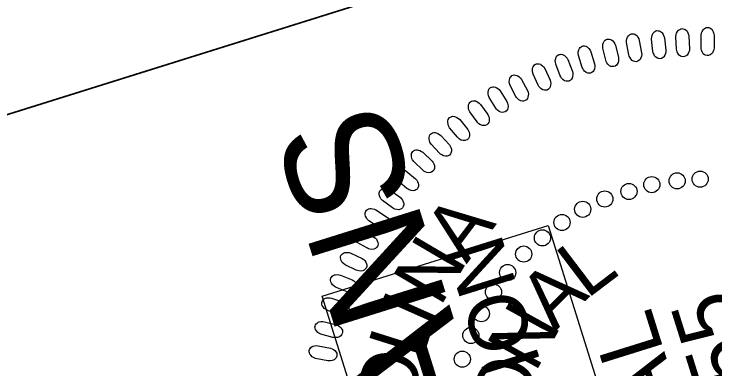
# Model space of a CAD drawing. Extents: x 473667 to 478950, y 494687 to 505998.
# Drawn here: x 473738.2 to 473807.7, y 505649.4 to 505684.6 of the extents above; entities that cross this region are included whole.
import ezdxf

# ---------------------------------------------------------------- set-up
doc = ezdxf.new("R2010")
doc.units = 0
for name, color, linetype in [('Sheet PE Seal Cell', 7, 'Continuous'), ('Sheet Plan CELL', 7, 'Continuous'), ('Sheet Plan Layout CELL', 7, 'Continuous'), ('Sheet Sticker Incomplete CELL', 7, 'Continuous')]:
    doc.layers.add(name, color=color, linetype=linetype)

msp = doc.modelspace()

# ---------------------------------------------------------------- linework, layer by layer
at = {"layer": 'Sheet PE Seal Cell'}
for points in [[(473803.877, 505681.09), (473803.813, 505682.316), (473803.839, 505682.536), (473803.883, 505682.679), (473803.987, 505682.854), (473804.078, 505682.968), (473804.187, 505683.054), (473804.288, 505683.099), (473804.4, 505683.124), (473804.512, 505683.111), (473804.634, 505683.087), (473804.741, 505683.033), (473804.851, 505682.938), (473804.915, 505682.862), (473804.99, 505682.716), (473805.059, 505682.54), (473805.09, 505682.382), (473805.162, 505681.127), (473805.148, 505680.956), (473805.111, 505680.815), (473805.03, 505680.651), (473804.925, 505680.506), (473804.833, 505680.421), (473804.678, 505680.353), (473804.53, 505680.325), (473804.379, 505680.357), (473804.272, 505680.402), (473804.139, 505680.495), (473804.012, 505680.658), (473803.934, 505680.834), (473803.899, 505680.961)], [(473806.306, 505681.251), (473806.32, 505682.478), (473806.359, 505682.697), (473806.413, 505682.837), (473806.527, 505683.005), (473806.625, 505683.113), (473806.739, 505683.192), (473806.843, 505683.231), (473806.955, 505683.249), (473807.067, 505683.228), (473807.187, 505683.196), (473807.291, 505683.136), (473807.394, 505683.035), (473807.453, 505682.955), (473807.519, 505682.804), (473807.577, 505682.624), (473807.598, 505682.464), (473807.591, 505681.208), (473807.567, 505681.039), (473807.52, 505680.899), (473807.429, 505680.741), (473807.316, 505680.602), (473807.218, 505680.523), (473807.06, 505680.465), (473806.91, 505680.447), (473806.761, 505680.489), (473806.657, 505680.54), (473806.531, 505680.641), (473806.414, 505680.812), (473806.348, 505680.992), (473806.32, 505681.121)], [(473799.142, 505680.527), (473798.925, 505681.735), (473798.924, 505681.957), (473798.95, 505682.104), (473799.03, 505682.291), (473799.107, 505682.416), (473799.203, 505682.514), (473799.299, 505682.572), (473799.406, 505682.611), (473799.519, 505682.611), (473799.643, 505682.603), (473799.756, 505682.563), (473799.877, 505682.483), (473799.95, 505682.415), (473800.043, 505682.28), (473800.133, 505682.114), (473800.183, 505681.96), (473800.412, 505680.725), (473800.421, 505680.554), (473800.401, 505680.409), (473800.341, 505680.236), (473800.255, 505680.079), (473800.174, 505679.983), (473800.03, 505679.896), (473799.886, 505679.85), (473799.732, 505679.863), (473799.62, 505679.894), (473799.477, 505679.969), (473799.33, 505680.115), (473799.232, 505680.28), (473799.18, 505680.402)], [(473801.538, 505680.862), (473801.399, 505682.08), (473801.41, 505682.302), (473801.445, 505682.447), (473801.538, 505682.629), (473801.622, 505682.749), (473801.724, 505682.841), (473801.824, 505682.893), (473801.933, 505682.925), (473802.046, 505682.918), (473802.169, 505682.902), (473802.28, 505682.855), (473802.395, 505682.767), (473802.464, 505682.695), (473802.548, 505682.555), (473802.627, 505682.383), (473802.668, 505682.227), (473802.819, 505680.98), (473802.816, 505680.809), (473802.788, 505680.665), (473802.717, 505680.496), (473802.622, 505680.344), (473802.534, 505680.254), (473802.385, 505680.177), (473802.239, 505680.14), (473802.086, 505680.162), (473801.976, 505680.2), (473801.838, 505680.284), (473801.701, 505680.439), (473801.613, 505680.61), (473801.569, 505680.735)], [(473796.86, 505679.987), (473796.567, 505681.178), (473796.552, 505681.399), (473796.569, 505681.548), (473796.637, 505681.74), (473796.706, 505681.87), (473796.796, 505681.973), (473796.887, 505682.037), (473796.992, 505682.083), (473797.105, 505682.09), (473797.229, 505682.09), (473797.345, 505682.057), (473797.47, 505681.984), (473797.547, 505681.921), (473797.648, 505681.792), (473797.749, 505681.632), (473797.809, 505681.482), (473798.115, 505680.263), (473798.134, 505680.094), (473798.123, 505679.947), (473798.075, 505679.771), (473797.998, 505679.609), (473797.923, 505679.508), (473797.785, 505679.412), (473797.644, 505679.357), (473797.49, 505679.361), (473797.376, 505679.384), (473797.229, 505679.451), (473797.073, 505679.587), (473796.964, 505679.746), (473796.905, 505679.864)], [(473794.52, 505679.288), (473794.154, 505680.46), (473794.125, 505680.68), (473794.133, 505680.829), (473794.189, 505681.024), (473794.249, 505681.158), (473794.332, 505681.267), (473794.42, 505681.336), (473794.522, 505681.389), (473794.634, 505681.403), (473794.757, 505681.411), (473794.875, 505681.385), (473795.005, 505681.321), (473795.085, 505681.263), (473795.195, 505681.14), (473795.305, 505680.987), (473795.374, 505680.841), (473795.757, 505679.644), (473795.786, 505679.476), (473795.784, 505679.328), (473795.746, 505679.149), (473795.682, 505678.983), (473795.613, 505678.878), (473795.481, 505678.774), (473795.344, 505678.71), (473795.189, 505678.704), (473795.075, 505678.72), (473794.923, 505678.777), (473794.759, 505678.904), (473794.641, 505679.055), (473794.573, 505679.169)], [(473792.341, 505678.45), (473791.903, 505679.595), (473791.859, 505679.813), (473791.857, 505679.962), (473791.901, 505680.161), (473791.953, 505680.298), (473792.03, 505680.412), (473792.113, 505680.487), (473792.21, 505680.546), (473792.322, 505680.567), (473792.444, 505680.582), (473792.563, 505680.564), (473792.697, 505680.508), (473792.781, 505680.455), (473792.898, 505680.34), (473793.018, 505680.193), (473793.096, 505680.053), (473793.553, 505678.882), (473793.592, 505678.715), (473793.6, 505678.569), (473793.574, 505678.388), (473793.519, 505678.218), (473793.457, 505678.108), (473793.332, 505677.996), (473793.199, 505677.924), (473793.046, 505677.908), (473792.93, 505677.917), (473792.775, 505677.964), (473792.604, 505678.08), (473792.476, 505678.223), (473792.402, 505678.334)], [(473790.157, 505677.51), (473789.648, 505678.626), (473789.59, 505678.841), (473789.579, 505678.99), (473789.611, 505679.19), (473789.654, 505679.331), (473789.722, 505679.45), (473789.801, 505679.53), (473789.895, 505679.594), (473790.005, 505679.623), (473790.126, 505679.645), (473790.247, 505679.635), (473790.383, 505679.587), (473790.47, 505679.54), (473790.594, 505679.431), (473790.723, 505679.293), (473790.81, 505679.157), (473791.34, 505678.018), (473791.389, 505677.854), (473791.406, 505677.708), (473791.391, 505677.526), (473791.347, 505677.352), (473791.292, 505677.24), (473791.175, 505677.119), (473791.046, 505677.039), (473790.894, 505677.014), (473790.778, 505677.016), (473790.621, 505677.053), (473790.442, 505677.158), (473790.306, 505677.293), (473790.225, 505677.399)], [(473787.949, 505676.401), (473787.37, 505677.482), (473787.299, 505677.693), (473787.279, 505677.841), (473787.298, 505678.044), (473787.332, 505678.186), (473787.393, 505678.31), (473787.466, 505678.394), (473787.556, 505678.465), (473787.664, 505678.5), (473787.784, 505678.53), (473787.904, 505678.527), (473788.043, 505678.488), (473788.134, 505678.447), (473788.264, 505678.346), (473788.401, 505678.216), (473788.496, 505678.086), (473789.097, 505676.982), (473789.157, 505676.821), (473789.183, 505676.677), (473789.179, 505676.494), (473789.146, 505676.319), (473789.099, 505676.202), (473788.988, 505676.075), (473788.865, 505675.987), (473788.715, 505675.952), (473788.6, 505675.946), (473788.44, 505675.974), (473788.255, 505676.067), (473788.11, 505676.194), (473788.024, 505676.294)], [(473785.95, 505675.241), (473785.305, 505676.284), (473785.221, 505676.489), (473785.191, 505676.636), (473785.197, 505676.84), (473785.222, 505676.984), (473785.276, 505677.11), (473785.343, 505677.199), (473785.428, 505677.275), (473785.534, 505677.318), (473785.652, 505677.355), (473785.771, 505677.36), (473785.913, 505677.33), (473786.006, 505677.294), (473786.142, 505677.202), (473786.288, 505677.08), (473786.391, 505676.957), (473787.059, 505675.892), (473787.129, 505675.737), (473787.164, 505675.594), (473787.172, 505675.411), (473787.151, 505675.234), (473787.11, 505675.114), (473787.008, 505674.981), (473786.891, 505674.885), (473786.743, 505674.841), (473786.628, 505674.828), (473786.468, 505674.846), (473786.277, 505674.927), (473786.125, 505675.044), (473786.031, 505675.139)], [(473784.099, 505673.88), (473783.389, 505674.881), (473783.292, 505675.081), (473783.254, 505675.225), (473783.248, 505675.429), (473783.263, 505675.574), (473783.308, 505675.704), (473783.37, 505675.797), (473783.451, 505675.878), (473783.553, 505675.927), (473783.668, 505675.972), (473783.788, 505675.984), (473783.931, 505675.963), (473784.026, 505675.933), (473784.168, 505675.849), (473784.32, 505675.738), (473784.432, 505675.621), (473785.165, 505674.6), (473785.244, 505674.449), (473785.288, 505674.309), (473785.308, 505674.128), (473785.298, 505673.949), (473785.264, 505673.827), (473785.171, 505673.687), (473785.061, 505673.585), (473784.915, 505673.531), (473784.802, 505673.511), (473784.64, 505673.519), (473784.445, 505673.587), (473784.285, 505673.695), (473784.186, 505673.783)], [(473782.152, 505672.354), (473781.38, 505673.308), (473781.272, 505673.502), (473781.224, 505673.643), (473781.205, 505673.845), (473781.212, 505673.992), (473781.249, 505674.125), (473781.305, 505674.222), (473781.379, 505674.308), (473781.479, 505674.362), (473781.591, 505674.415), (473781.709, 505674.434), (473781.854, 505674.422), (473781.951, 505674.398), (473782.097, 505674.324), (473782.257, 505674.222), (473782.374, 505674.112), (473783.17, 505673.14), (473783.26, 505672.994), (473783.313, 505672.857), (473783.343, 505672.677), (473783.344, 505672.498), (473783.319, 505672.374), (473783.234, 505672.229), (473783.13, 505672.12), (473782.989, 505672.057), (473782.876, 505672.03), (473782.715, 505672.027), (473782.515, 505672.084), (473782.35, 505672.181), (473782.245, 505672.263)], [(473780.383, 505670.774), (473779.552, 505671.677), (473779.432, 505671.864), (473779.375, 505672.002), (473779.344, 505672.203), (473779.341, 505672.349), (473779.37, 505672.484), (473779.42, 505672.584), (473779.489, 505672.675), (473779.585, 505672.736), (473779.693, 505672.794), (473779.81, 505672.822), (473779.955, 505672.819), (473780.053, 505672.801), (473780.204, 505672.736), (473780.369, 505672.644), (473780.494, 505672.541), (473781.35, 505671.621), (473781.447, 505671.481), (473781.509, 505671.348), (473781.551, 505671.17), (473781.563, 505670.991), (473781.546, 505670.867), (473781.47, 505670.716), (473781.373, 505670.6), (473781.237, 505670.529), (473781.126, 505670.495), (473780.965, 505670.482), (473780.762, 505670.526), (473780.591, 505670.613), (473780.481, 505670.689)], [(473778.726, 505669.094), (473777.841, 505669.944), (473777.709, 505670.123), (473777.644, 505670.256), (473777.599, 505670.455), (473777.587, 505670.601), (473777.608, 505670.737), (473777.652, 505670.841), (473777.714, 505670.935), (473777.807, 505671.002), (473777.911, 505671.068), (473778.026, 505671.102), (473778.171, 505671.109), (473778.27, 505671.096), (473778.424, 505671.041), (473778.595, 505670.96), (473778.726, 505670.866), (473779.638, 505670.001), (473779.744, 505669.867), (473779.814, 505669.738), (473779.867, 505669.563), (473779.89, 505669.386), (473779.881, 505669.26), (473779.815, 505669.106), (473779.726, 505668.984), (473779.594, 505668.904), (473779.485, 505668.862), (473779.325, 505668.84), (473779.12, 505668.871), (473778.944, 505668.947), (473778.829, 505669.015)], [(473777.147, 505667.278), (473776.21, 505668.07), (473776.067, 505668.241), (473775.993, 505668.37), (473775.936, 505668.565), (473775.915, 505668.711), (473775.927, 505668.848), (473775.964, 505668.954), (473776.021, 505669.052), (473776.109, 505669.125), (473776.209, 505669.197), (473776.322, 505669.238), (473776.466, 505669.253), (473776.566, 505669.248), (473776.724, 505669.202), (473776.899, 505669.132), (473777.035, 505669.046), (473778, 505668.241), (473778.114, 505668.114), (473778.192, 505667.989), (473778.256, 505667.818), (473778.29, 505667.642), (473778.289, 505667.516), (473778.233, 505667.358), (473778.151, 505667.231), (473778.025, 505667.143), (473777.919, 505667.095), (473777.76, 505667.062), (473777.554, 505667.08), (473777.373, 505667.145), (473777.255, 505667.206)], [(473775.708, 505665.359), (473774.724, 505666.092), (473774.57, 505666.252), (473774.489, 505666.377), (473774.42, 505666.569), (473774.39, 505666.712), (473774.393, 505666.849), (473774.423, 505666.958), (473774.474, 505667.06), (473774.557, 505667.138), (473774.652, 505667.216), (473774.763, 505667.264), (473774.905, 505667.288), (473775.005, 505667.289), (473775.166, 505667.254), (473775.345, 505667.195), (473775.486, 505667.118), (473776.499, 505666.374), (473776.622, 505666.255), (473776.708, 505666.135), (473776.782, 505665.968), (473776.827, 505665.795), (473776.833, 505665.669), (473776.788, 505665.508), (473776.714, 505665.375), (473776.593, 505665.28), (473776.491, 505665.226), (473776.335, 505665.182), (473776.128, 505665.188), (473775.943, 505665.241), (473775.821, 505665.295)], [(473774.406, 505663.421), (473773.377, 505664.09), (473773.214, 505664.241), (473773.125, 505664.361), (473773.044, 505664.547), (473773.005, 505664.689), (473772.999, 505664.826), (473773.023, 505664.936), (473773.067, 505665.041), (473773.145, 505665.124), (473773.236, 505665.208), (473773.343, 505665.263), (473773.483, 505665.296), (473773.583, 505665.303), (473773.745, 505665.277), (473773.928, 505665.23), (473774.074, 505665.162), (473775.132, 505664.483), (473775.261, 505664.372), (473775.354, 505664.258), (473775.439, 505664.096), (473775.495, 505663.926), (473775.509, 505663.801), (473775.474, 505663.636), (473775.409, 505663.5), (473775.294, 505663.397), (473775.195, 505663.336), (473775.042, 505663.284), (473774.835, 505663.276), (473774.647, 505663.318), (473774.523, 505663.363)], [(473773.221, 505661.361), (473772.153, 505661.964), (473771.981, 505662.104), (473771.884, 505662.218), (473771.792, 505662.399), (473771.744, 505662.537), (473771.729, 505662.674), (473771.746, 505662.785), (473771.783, 505662.893), (473771.856, 505662.981), (473771.941, 505663.07), (473772.044, 505663.132), (473772.183, 505663.174), (473772.282, 505663.187), (473772.445, 505663.172), (473772.63, 505663.136), (473772.781, 505663.077), (473773.879, 505662.466), (473774.015, 505662.363), (473774.115, 505662.256), (473774.21, 505662.099), (473774.276, 505661.933), (473774.299, 505661.809), (473774.273, 505661.643), (473774.217, 505661.503), (473774.109, 505661.392), (473774.014, 505661.326), (473773.865, 505661.264), (473773.659, 505661.243), (473773.469, 505661.273), (473773.341, 505661.311)], [(473772.127, 505659.19), (473771.022, 505659.725), (473770.841, 505659.854), (473770.738, 505659.962), (473770.634, 505660.136), (473770.578, 505660.272), (473770.555, 505660.407), (473770.565, 505660.519), (473770.596, 505660.629), (473770.662, 505660.721), (473770.742, 505660.815), (473770.841, 505660.884), (473770.976, 505660.934), (473771.075, 505660.954), (473771.238, 505660.949), (473771.426, 505660.925), (473771.579, 505660.875), (473772.714, 505660.334), (473772.856, 505660.24), (473772.962, 505660.139), (473773.067, 505659.989), (473773.144, 505659.828), (473773.173, 505659.705), (473773.159, 505659.537), (473773.112, 505659.394), (473773.01, 505659.278), (473772.92, 505659.205), (473772.775, 505659.134), (473772.57, 505659.1), (473772.38, 505659.118), (473772.25, 505659.148)], [(473771.212, 505657.047), (473770.076, 505657.511), (473769.887, 505657.628), (473769.778, 505657.729), (473769.663, 505657.898), (473769.598, 505658.029), (473769.567, 505658.163), (473769.569, 505658.275), (473769.594, 505658.387), (473769.654, 505658.482), (473769.727, 505658.582), (473769.822, 505658.656), (473769.954, 505658.715), (473770.05, 505658.741), (473770.214, 505658.746), (473770.403, 505658.734), (473770.559, 505658.695), (473771.725, 505658.226), (473771.874, 505658.141), (473771.986, 505658.046), (473772.1, 505657.903), (473772.187, 505657.746), (473772.225, 505657.626), (473772.221, 505657.458), (473772.182, 505657.313), (473772.089, 505657.189), (473772.003, 505657.111), (473771.862, 505657.032), (473771.661, 505656.985), (473771.468, 505656.99), (473771.337, 505657.012)], [(473770.427, 505654.816), (473769.264, 505655.207), (473769.068, 505655.313), (473768.952, 505655.407), (473768.827, 505655.567), (473768.755, 505655.694), (473768.715, 505655.826), (473768.71, 505655.939), (473768.727, 505656.051), (473768.782, 505656.151), (473768.848, 505656.254), (473768.938, 505656.334), (473769.067, 505656.402), (473769.161, 505656.433), (473769.325, 505656.449), (473769.514, 505656.449), (473769.672, 505656.419), (473770.865, 505656.024), (473771.019, 505655.949), (473771.137, 505655.862), (473771.259, 505655.726), (473771.356, 505655.575), (473771.4, 505655.457), (473771.407, 505655.29), (473771.378, 505655.142), (473771.293, 505655.013), (473771.212, 505654.93), (473771.077, 505654.841), (473770.878, 505654.782), (473770.686, 505654.775), (473770.554, 505654.788)], [(473769.809, 505652.527), (473768.625, 505652.845), (473768.422, 505652.938), (473768.301, 505653.024), (473768.166, 505653.176), (473768.085, 505653.299), (473768.038, 505653.428), (473768.026, 505653.539), (473768.036, 505653.653), (473768.084, 505653.756), (473768.145, 505653.863), (473768.229, 505653.949), (473768.353, 505654.025), (473768.445, 505654.061), (473768.608, 505654.088), (473768.796, 505654.099), (473768.956, 505654.079), (473770.172, 505653.761), (473770.329, 505653.695), (473770.453, 505653.615), (473770.583, 505653.488), (473770.689, 505653.344), (473770.742, 505653.229), (473770.759, 505653.061), (473770.739, 505652.912), (473770.662, 505652.778), (473770.586, 505652.69), (473770.457, 505652.592), (473770.263, 505652.521), (473770.072, 505652.503), (473769.938, 505652.508)], [(473769.294, 505650.209), (473768.092, 505650.451), (473767.884, 505650.532), (473767.757, 505650.61), (473767.614, 505650.754), (473767.525, 505650.871), (473767.469, 505650.997), (473767.451, 505651.107), (473767.453, 505651.221), (473767.495, 505651.327), (473767.548, 505651.438), (473767.628, 505651.529), (473767.746, 505651.612), (473767.836, 505651.654), (473767.996, 505651.691), (473768.184, 505651.714), (473768.345, 505651.705), (473769.578, 505651.463), (473769.74, 505651.407), (473769.868, 505651.336), (473770.006, 505651.216), (473770.121, 505651.078), (473770.18, 505650.968), (473770.208, 505650.802), (473770.198, 505650.651), (473770.129, 505650.512), (473770.059, 505650.42), (473769.936, 505650.315), (473769.746, 505650.231), (473769.557, 505650.201), (473769.424, 505650.197)]]:
    msp.add_lwpolyline(points, close=True, dxfattribs=at)
for centre in [(473803.935, 505668.037), (473806.219, 505668.209), (473801.421, 505667.667), (473799.157, 505666.989), (473796.761, 505666.24), (473794.575, 505665.222), (473792.522, 505663.912), (473790.579, 505662.386), (473788.723, 505660.786), (473787.127, 505658.951), (473785.73, 505657.012), (473784.518, 505654.881), (473783.483, 505652.722), (473782.632, 505650.37)]:
    msp.add_circle(centre, 0.801, dxfattribs=at)
at = {"layer": 'Sheet Plan CELL'}
for points in [[(473693.706, 505660.898), (474142.147, 504229.461), (475144.128, 504543.362), (474695.694, 505974.775)], [(473759.453, 505576.677), (473729.55, 505672.088), (473836.913, 505705.736), (473866.82, 505610.313)]]:
    msp.add_lwpolyline(points, close=True, dxfattribs=at)
at = {"layer": 'Sheet Plan Layout CELL'}
msp.add_lwpolyline([(473967.057, 505495.778), (473895.525, 505724.111), (473693.702, 505660.91), (473765.242, 505432.554)], close=True, dxfattribs=at)
at = {"layer": 'Sheet Sticker Incomplete CELL'}
msp.add_lwpolyline([(473835.104, 505523.354), (473812.679, 505516.329), (473768.733, 505656.606), (473791.158, 505663.632)], close=True, dxfattribs=at)

# ---------------------------------------------------------------- texts
at = {"layer": 'Sheet PE Seal Cell'}
for s, height, rotation, p in [('A', 5.669, 53.06758, (473783.048, 505659.755)), ('N', 5.669, 59.55694, (473780.433, 505655.456)), ('L', 5.669, 37.22561, (473794.969, 505656.267)), ('A', 5.669, 45.16541, (473791.792, 505653.046)), ('I', 5.669, 66.04629, (473779.617, 505653.309)), ('46155', 6.2363, 107.37612, (473816.048, 505635.447)), ('N', 5.669, 61.04501, (473789.85, 505648.941)), ('SEAL', 6.2363, 107.37612, (473807.637, 505635.273)), ('L', 5.669, 72.53565, (473778.654, 505650.185)), ('O', 5.669, 79.02501, (473777.653, 505644.912)), ('O', 5.669, 76.9246, (473788.94, 505644.137))]:
    msp.add_text(s, height=height, rotation=rotation, dxfattribs=at).set_placement(p)
at = {"layer": 'Sheet Sticker Incomplete CELL'}
for s, height, p in [('INCOMPLETE PLANS', 11.52, (473821.263, 505528.397)), ('DO NOT USE FOR R/W ACQUISITION', 5.76, (473826.924, 505533.576))]:
    msp.add_text(s, height=height, rotation=107.39476, dxfattribs=at).set_placement(p)

doc.saveas('drawing.dxf')
